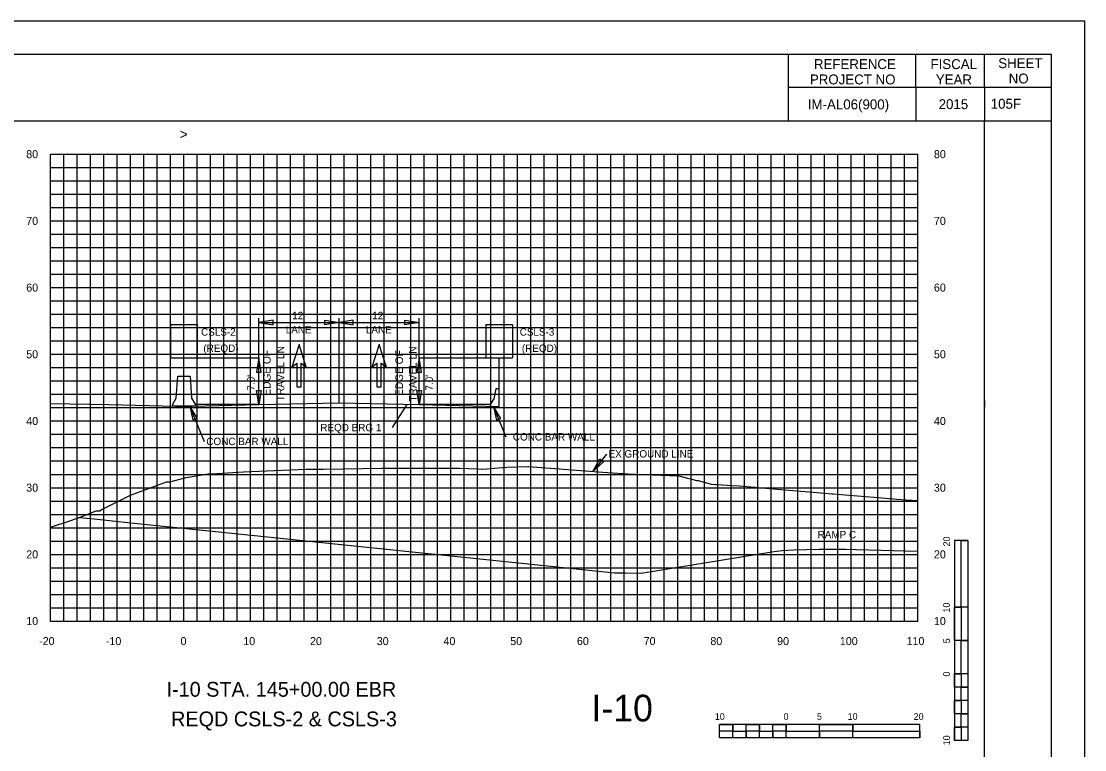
# Model space of a CAD drawing. Extents: x 2193008 to 2198143, y 1236112 to 1237864.
# Drawn here: x 2195038.5 to 2195197.9, y 1237228.8 to 1237338 of the extents above; entities that cross this region are included whole.
import ezdxf

# ---------------------------------------------------------------- set-up
doc = ezdxf.new("R2010")
doc.units = 0
for name, color, linetype in [('10', 7, 'Continuous'), ('2', 7, 'Continuous'), ('3', 7, 'Continuous'), ('31', 7, 'Continuous'), ('60', 7, 'Continuous'), ('ANNO-SHT', 7, 'Continuous'), ('CL-CNST', 7, 'Continuous'), ('GSDIMS', 7, 'Continuous'), ('Level 1', 7, 'Continuous'), ('Level 28', 7, 'Continuous'), ('Level 33', 7, 'Continuous'), ('Level 55', 7, 'Continuous'), ('Level 6', 7, 'Continuous'), ('Level 62', 7, 'Continuous'), ('M-ROADS', 7, 'Continuous'), ('SHT-BDR', 7, 'Continuous'), ('SHT-BNDRY', 7, 'Continuous')]:
    doc.layers.add(name, color=color, linetype=linetype)

msp = doc.modelspace()

# ---------------------------------------------------------------- linework, layer by layer
for points in [[(2195061.19, 1237280.61), (2195061.72, 1237281.52), (2195061.94, 1237284.85), (2195063.78, 1237284.85), (2195064, 1237281.52), (2195064.53, 1237280.61), (2195064.53, 1237280.35), (2195061.19, 1237280.35)], [(2195110.11, 1237280.29), (2195110.1, 1237282.94), (2195109.6, 1237282.94), (2195109.32, 1237281.41), (2195108.74, 1237280.58), (2195108.74, 1237280.32)]]:
    msp.add_lwpolyline(points, close=True)
at = {"layer": '2'}
msp.add_lwpolyline([(2195182.83, 1237281.19), (2195182.84, 1237280.19)], dxfattribs=at)
msp.add_lwpolyline([(2195182.83, 1237281.19), (2195182.84, 1237280.19)], dxfattribs=at)
at = {"layer": '3'}
for p, q in [((2195074.11, 1237280.56), (2195074.11, 1237293.53)), ((2195086.11, 1237280.82), (2195086.11, 1237293.53)), ((2195098.11, 1237280.56), (2195098.11, 1237293.53)), ((2195062.86, 1237284.85), (2195062.86, 1237287.56)), ((2195110.1, 1237282.94), (2195110.1, 1237287.56)), ((2195065.95, 1237274.99), (2195063.74, 1237280.35)), ((2195094.1, 1237277.11), (2195096.3, 1237280.6)), ((2195111.15, 1237275.68), (2195109.24, 1237280.3)), ((2195126.18, 1237273.12), (2195124.16, 1237270.56))]:
    msp.add_line(p, q, dxfattribs=at)
at = {"layer": '60'}
for p, q in [((2195042.86, 1237248.11), (2195042.86, 1237318.11)), ((2195172.86, 1237248.11), (2195172.86, 1237318.11)), ((2195172.92, 1237308.11), (2195172.86, 1237308.11)), ((2195172.92, 1237298.11), (2195172.86, 1237298.11)), ((2195172.92, 1237288.11), (2195172.86, 1237288.11)), ((2195172.92, 1237278.11), (2195172.86, 1237278.11)), ((2195172.92, 1237268.11), (2195172.86, 1237268.11)), ((2195172.92, 1237258.11), (2195172.86, 1237258.11)), ((2195042.86, 1237248.05), (2195042.86, 1237248.11)), ((2195042.86, 1237248.11), (2195172.86, 1237248.11)), ((2195052.86, 1237248.05), (2195052.86, 1237248.11)), ((2195062.86, 1237248.05), (2195062.86, 1237248.11)), ((2195072.86, 1237248.05), (2195072.86, 1237248.11)), ((2195082.86, 1237248.05), (2195082.86, 1237248.11)), ((2195092.86, 1237248.05), (2195092.86, 1237248.11)), ((2195102.86, 1237248.05), (2195102.86, 1237248.11)), ((2195112.86, 1237248.05), (2195112.86, 1237248.11)), ((2195122.86, 1237248.05), (2195122.86, 1237248.11)), ((2195132.86, 1237248.05), (2195132.86, 1237248.11)), ((2195142.86, 1237248.05), (2195142.86, 1237248.11)), ((2195152.86, 1237248.05), (2195152.86, 1237248.11)), ((2195162.86, 1237248.05), (2195162.86, 1237248.11)), ((2195172.86, 1237248.05), (2195172.86, 1237248.11)), ((2195172.92, 1237248.11), (2195172.86, 1237248.11))]:
    msp.add_line(p, q, dxfattribs=at)
at = {"layer": 'CL-CNST'}
for points in [[(2195042.86, 1237280.75), (2195051.61, 1237280.56), (2195061.61, 1237280.34), (2195062.86, 1237280.31)], [(2195062.86, 1237280.31), (2195064.11, 1237280.34), (2195074.11, 1237280.56), (2195086.11, 1237280.82), (2195098.11, 1237280.56), (2195110.11, 1237280.29)], [(2195047.23, 1237263.66), (2195049.42, 1237263.44), (2195054.92, 1237262.86), (2195073.44, 1237260.94), (2195116.86, 1237256.42), (2195127.39, 1237255.32), (2195129.05, 1237255.32), (2195131.41, 1237255.31), (2195150.98, 1237258.47), (2195152.49, 1237258.71), (2195154.2, 1237258.77), (2195158.02, 1237258.91), (2195158.09, 1237258.91), (2195162.03, 1237258.88), (2195163.68, 1237258.84), (2195172.86, 1237258.6)]]:
    msp.add_lwpolyline(points, dxfattribs=at)
at = {"layer": 'GSDIMS'}
for p, q in [((2195060.86, 1237292.56), (2195064.86, 1237292.56)), ((2195060.86, 1237292.56), (2195060.86, 1237287.56)), ((2195064.86, 1237292.56), (2195064.86, 1237287.56)), ((2195074.11, 1237292.87), (2195086.11, 1237292.87)), ((2195086.11, 1237292.87), (2195098.11, 1237292.87)), ((2195108.1, 1237292.56), (2195112.1, 1237292.56)), ((2195108.1, 1237292.56), (2195108.1, 1237287.56)), ((2195112.1, 1237292.56), (2195112.1, 1237287.56)), ((2195060.86, 1237287.56), (2195064.86, 1237287.56)), ((2195064.86, 1237287.56), (2195074.11, 1237287.56)), ((2195098.11, 1237287.56), (2195108.1, 1237287.56)), ((2195108.1, 1237287.56), (2195112.1, 1237287.56)), ((2195074.11, 1237280.56), (2195064.53, 1237280.56)), ((2195108.74, 1237280.56), (2195098.11, 1237280.56))]:
    msp.add_line(p, q, dxfattribs=at)
for points in [[(2195074.11, 1237292.87), (2195076.24, 1237292.52), (2195076.24, 1237293.21)], [(2195086.11, 1237292.87), (2195083.98, 1237292.52), (2195083.98, 1237293.21)], [(2195086.11, 1237292.87), (2195088.24, 1237292.52), (2195088.24, 1237293.21)], [(2195098.11, 1237292.87), (2195095.98, 1237292.52), (2195095.98, 1237293.21)], [(2195074.11, 1237287.56), (2195073.76, 1237285.43), (2195074.46, 1237285.43)], [(2195098.11, 1237287.56), (2195097.76, 1237285.43), (2195098.46, 1237285.43)], [(2195074.11, 1237280.56), (2195073.76, 1237282.69), (2195074.46, 1237282.69)], [(2195098.11, 1237280.56), (2195097.76, 1237282.69), (2195098.46, 1237282.69)], [(2195063.74, 1237280.35), (2195064.22, 1237278.26), (2195064.86, 1237278.54)], [(2195109.24, 1237280.3), (2195109.72, 1237278.22), (2195110.37, 1237278.5)], [(2195124.16, 1237270.56), (2195125.19, 1237272.44), (2195125.73, 1237271.99)]]:
    msp.add_lwpolyline(points, close=True, dxfattribs=at)
at = {"layer": 'Level 1'}
for p, q in [((2195178.33, 1237260.19), (2195178.33, 1237230.19)), ((2195180.33, 1237260.19), (2195178.33, 1237260.19)), ((2195180.33, 1237260.19), (2195180.33, 1237250.19)), ((2195180.33, 1237260.19), (2195180.33, 1237230.19)), ((2195179.33, 1237250.19), (2195178.33, 1237250.19)), ((2195180.33, 1237250.19), (2195178.33, 1237250.19)), ((2195179.33, 1237250.19), (2195179.33, 1237245.19)), ((2195180.33, 1237245.19), (2195178.33, 1237245.19)), ((2195180.33, 1237245.19), (2195179.33, 1237245.19)), ((2195180.33, 1237245.19), (2195180.33, 1237240.19)), ((2195179.33, 1237240.19), (2195178.33, 1237240.19)), ((2195180.33, 1237240.19), (2195178.33, 1237240.19)), ((2195179.33, 1237240.19), (2195179.33, 1237238.19)), ((2195180.33, 1237238.19), (2195179.33, 1237238.19)), ((2195180.33, 1237238.19), (2195180.33, 1237236.19)), ((2195179.33, 1237236.19), (2195178.33, 1237236.19)), ((2195179.33, 1237236.19), (2195179.33, 1237234.19)), ((2195180.33, 1237234.19), (2195179.33, 1237234.19)), ((2195180.33, 1237234.19), (2195180.33, 1237232.19)), ((2195173.13, 1237232.63), (2195143.13, 1237232.63)), ((2195143.13, 1237230.63), (2195143.13, 1237232.63)), ((2195145.13, 1237231.63), (2195145.13, 1237232.63)), ((2195149.13, 1237231.63), (2195149.13, 1237232.63)), ((2195153.13, 1237231.63), (2195153.13, 1237232.63)), ((2195153.13, 1237230.63), (2195153.13, 1237232.63)), ((2195158.13, 1237230.63), (2195158.13, 1237232.63)), ((2195163.13, 1237231.63), (2195163.13, 1237232.63)), ((2195163.13, 1237230.63), (2195163.13, 1237232.63)), ((2195173.13, 1237230.63), (2195173.13, 1237232.63)), ((2195145.13, 1237231.63), (2195143.13, 1237231.63)), ((2195147.13, 1237230.63), (2195147.13, 1237231.63)), ((2195149.13, 1237231.63), (2195147.13, 1237231.63)), ((2195151.13, 1237230.63), (2195151.13, 1237231.63)), ((2195153.13, 1237231.63), (2195151.13, 1237231.63)), ((2195158.13, 1237230.63), (2195158.13, 1237231.63)), ((2195163.13, 1237231.63), (2195158.13, 1237231.63)), ((2195179.33, 1237232.19), (2195178.33, 1237232.19)), ((2195179.33, 1237232.19), (2195179.33, 1237230.19)), ((2195173.13, 1237230.63), (2195143.13, 1237230.63)), ((2195147.13, 1237230.63), (2195145.13, 1237230.63)), ((2195151.13, 1237230.63), (2195149.13, 1237230.63)), ((2195158.13, 1237230.63), (2195153.13, 1237230.63)), ((2195173.13, 1237230.63), (2195163.13, 1237230.63)), ((2195180.33, 1237230.19), (2195178.33, 1237230.19))]:
    msp.add_line(p, q, dxfattribs=at)
for points in [[(2195179.33, 1237250.19), (2195179.33, 1237260.19), (2195180.33, 1237260.19), (2195180.33, 1237250.19)], [(2195178.33, 1237245.19), (2195178.33, 1237250.19), (2195179.33, 1237250.19), (2195179.33, 1237245.19)], [(2195179.33, 1237240.19), (2195179.33, 1237245.19), (2195180.33, 1237245.19), (2195180.33, 1237240.19)], [(2195178.33, 1237238.19), (2195178.33, 1237240.19), (2195179.33, 1237240.19), (2195179.33, 1237238.19)], [(2195179.33, 1237236.19), (2195179.33, 1237238.19), (2195180.33, 1237238.19), (2195180.33, 1237236.19)], [(2195178.33, 1237234.19), (2195178.33, 1237236.19), (2195179.33, 1237236.19), (2195179.33, 1237234.19)], [(2195179.33, 1237232.19), (2195179.33, 1237234.19), (2195180.33, 1237234.19), (2195180.33, 1237232.19)], [(2195143.13, 1237232.63), (2195145.13, 1237232.63), (2195145.13, 1237231.63), (2195143.13, 1237231.63)], [(2195147.13, 1237232.63), (2195149.13, 1237232.63), (2195149.13, 1237231.63), (2195147.13, 1237231.63)], [(2195151.13, 1237232.63), (2195153.13, 1237232.63), (2195153.13, 1237231.63), (2195151.13, 1237231.63)], [(2195158.13, 1237232.63), (2195163.13, 1237232.63), (2195163.13, 1237231.63), (2195158.13, 1237231.63)], [(2195145.13, 1237231.63), (2195147.13, 1237231.63), (2195147.13, 1237230.63), (2195145.13, 1237230.63)], [(2195149.13, 1237231.63), (2195151.13, 1237231.63), (2195151.13, 1237230.63), (2195149.13, 1237230.63)], [(2195153.13, 1237231.63), (2195158.13, 1237231.63), (2195158.13, 1237230.63), (2195153.13, 1237230.63)], [(2195163.13, 1237231.63), (2195173.13, 1237231.63), (2195173.13, 1237230.63), (2195163.13, 1237230.63)], [(2195178.33, 1237230.19), (2195178.33, 1237232.19), (2195179.33, 1237232.19), (2195179.33, 1237230.19)]]:
    msp.add_lwpolyline(points, close=True, dxfattribs=at)
at = {"layer": 'Level 28'}
for p, q in [((2195080.11, 1237289.56), (2195079.02, 1237286.16)), ((2195081.2, 1237286.16), (2195080.11, 1237289.56)), ((2195092.11, 1237289.56), (2195091.02, 1237286.16)), ((2195093.2, 1237286.16), (2195092.11, 1237289.56)), ((2195079.02, 1237286.16), (2195079.78, 1237286.8)), ((2195079.78, 1237286.8), (2195079.78, 1237283.23)), ((2195080.44, 1237283.23), (2195080.44, 1237286.8)), ((2195080.44, 1237286.8), (2195081.2, 1237286.16)), ((2195091.02, 1237286.16), (2195091.78, 1237286.8)), ((2195091.78, 1237286.8), (2195091.78, 1237283.23)), ((2195092.44, 1237283.23), (2195092.44, 1237286.8)), ((2195092.44, 1237286.8), (2195093.2, 1237286.16)), ((2195079.78, 1237283.23), (2195080.44, 1237283.23)), ((2195091.78, 1237283.23), (2195092.44, 1237283.23))]:
    msp.add_line(p, q, dxfattribs=at)
at = {"layer": 'Level 6'}
for p, q in [((2195153.41, 1237333.04), (2195153.41, 1237323.05)), ((2195172.57, 1237328.04), (2195172.57, 1237333.04)), ((2195182.86, 1237328.17), (2195182.86, 1237333.04)), ((2195192.86, 1237328.1), (2195153.41, 1237328.1)), ((2195182.86, 1237328.17), (2195182.86, 1237323.05)), ((2195172.57, 1237328.04), (2195172.57, 1237323.05)), ((2195192.86, 1237323.05), (2195154.62, 1237323.05))]:
    msp.add_line(p, q, dxfattribs=at)
at = {"layer": 'Level 62'}
for p, q in [((2195042.86, 1237318.11), (2195172.86, 1237318.11)), ((2195044.86, 1237248.11), (2195044.86, 1237318.11)), ((2195046.86, 1237248.11), (2195046.86, 1237318.11)), ((2195048.86, 1237248.11), (2195048.86, 1237318.11)), ((2195050.86, 1237248.11), (2195050.86, 1237318.11)), ((2195052.86, 1237248.11), (2195052.86, 1237318.11)), ((2195054.86, 1237248.11), (2195054.86, 1237318.11)), ((2195056.86, 1237248.11), (2195056.86, 1237318.11)), ((2195058.86, 1237248.11), (2195058.86, 1237318.11)), ((2195060.86, 1237248.11), (2195060.86, 1237318.11)), ((2195062.86, 1237248.11), (2195062.86, 1237318.11)), ((2195064.86, 1237248.11), (2195064.86, 1237318.11)), ((2195066.86, 1237248.11), (2195066.86, 1237318.11)), ((2195068.86, 1237248.11), (2195068.86, 1237318.11)), ((2195070.86, 1237248.11), (2195070.86, 1237318.11)), ((2195072.86, 1237248.11), (2195072.86, 1237318.11)), ((2195074.86, 1237248.11), (2195074.86, 1237318.11)), ((2195076.86, 1237248.11), (2195076.86, 1237318.11)), ((2195078.86, 1237248.11), (2195078.86, 1237318.11)), ((2195080.86, 1237248.11), (2195080.86, 1237318.11)), ((2195082.86, 1237248.11), (2195082.86, 1237318.11)), ((2195084.86, 1237248.11), (2195084.86, 1237318.11)), ((2195086.86, 1237248.11), (2195086.86, 1237318.11)), ((2195088.86, 1237248.11), (2195088.86, 1237318.11)), ((2195090.86, 1237248.11), (2195090.86, 1237318.11)), ((2195092.86, 1237248.11), (2195092.86, 1237318.11)), ((2195094.86, 1237248.11), (2195094.86, 1237318.11)), ((2195096.86, 1237248.11), (2195096.86, 1237318.11)), ((2195098.86, 1237248.11), (2195098.86, 1237318.11)), ((2195100.86, 1237248.11), (2195100.86, 1237318.11)), ((2195102.86, 1237248.11), (2195102.86, 1237318.11)), ((2195104.86, 1237248.11), (2195104.86, 1237318.11)), ((2195106.86, 1237248.11), (2195106.86, 1237318.11)), ((2195108.86, 1237248.11), (2195108.86, 1237318.11)), ((2195110.86, 1237248.11), (2195110.86, 1237318.11)), ((2195112.86, 1237248.11), (2195112.86, 1237318.11)), ((2195114.86, 1237248.11), (2195114.86, 1237318.11)), ((2195116.86, 1237248.11), (2195116.86, 1237318.11)), ((2195118.86, 1237248.11), (2195118.86, 1237318.11)), ((2195120.86, 1237248.11), (2195120.86, 1237318.11)), ((2195122.86, 1237248.11), (2195122.86, 1237318.11)), ((2195124.86, 1237248.11), (2195124.86, 1237318.11)), ((2195126.86, 1237248.11), (2195126.86, 1237318.11)), ((2195128.86, 1237248.11), (2195128.86, 1237318.11)), ((2195130.86, 1237248.11), (2195130.86, 1237318.11)), ((2195132.86, 1237248.11), (2195132.86, 1237318.11)), ((2195134.86, 1237248.11), (2195134.86, 1237318.11)), ((2195136.86, 1237248.11), (2195136.86, 1237318.11)), ((2195138.86, 1237248.11), (2195138.86, 1237318.11)), ((2195140.86, 1237248.11), (2195140.86, 1237318.11)), ((2195142.86, 1237248.11), (2195142.86, 1237318.11)), ((2195144.86, 1237248.11), (2195144.86, 1237318.11)), ((2195146.86, 1237248.11), (2195146.86, 1237318.11)), ((2195148.86, 1237248.11), (2195148.86, 1237318.11)), ((2195150.86, 1237248.11), (2195150.86, 1237318.11)), ((2195152.86, 1237248.11), (2195152.86, 1237318.11)), ((2195154.86, 1237248.11), (2195154.86, 1237318.11)), ((2195156.86, 1237248.11), (2195156.86, 1237318.11)), ((2195158.86, 1237248.11), (2195158.86, 1237318.11)), ((2195160.86, 1237248.11), (2195160.86, 1237318.11)), ((2195162.86, 1237248.11), (2195162.86, 1237318.11)), ((2195164.86, 1237248.11), (2195164.86, 1237318.11)), ((2195166.86, 1237248.11), (2195166.86, 1237318.11)), ((2195168.86, 1237248.11), (2195168.86, 1237318.11)), ((2195170.86, 1237248.11), (2195170.86, 1237318.11)), ((2195172.86, 1237248.11), (2195172.86, 1237318.11)), ((2195042.86, 1237316.11), (2195172.86, 1237316.11)), ((2195042.86, 1237314.11), (2195172.86, 1237314.11)), ((2195042.86, 1237312.11), (2195172.86, 1237312.11)), ((2195042.86, 1237310.11), (2195172.86, 1237310.11)), ((2195042.86, 1237308.11), (2195172.86, 1237308.11)), ((2195042.86, 1237306.11), (2195172.86, 1237306.11)), ((2195042.86, 1237304.11), (2195172.86, 1237304.11)), ((2195042.86, 1237302.11), (2195172.86, 1237302.11)), ((2195042.86, 1237300.11), (2195172.86, 1237300.11)), ((2195042.86, 1237298.11), (2195172.86, 1237298.11)), ((2195042.86, 1237296.11), (2195172.86, 1237296.11)), ((2195042.86, 1237294.11), (2195172.86, 1237294.11)), ((2195042.86, 1237292.11), (2195172.86, 1237292.11)), ((2195042.86, 1237290.11), (2195172.86, 1237290.11)), ((2195042.86, 1237288.11), (2195172.86, 1237288.11)), ((2195042.86, 1237286.11), (2195172.86, 1237286.11)), ((2195042.86, 1237284.11), (2195172.86, 1237284.11)), ((2195042.86, 1237282.11), (2195172.86, 1237282.11)), ((2195042.86, 1237280.11), (2195172.86, 1237280.11)), ((2195042.86, 1237278.11), (2195172.86, 1237278.11)), ((2195042.86, 1237276.11), (2195172.86, 1237276.11)), ((2195042.86, 1237274.11), (2195172.86, 1237274.11)), ((2195042.86, 1237272.11), (2195172.86, 1237272.11)), ((2195042.86, 1237270.11), (2195172.86, 1237270.11)), ((2195042.86, 1237268.11), (2195172.86, 1237268.11)), ((2195042.86, 1237266.11), (2195172.86, 1237266.11)), ((2195042.86, 1237264.11), (2195172.86, 1237264.11)), ((2195042.86, 1237262.11), (2195172.86, 1237262.11)), ((2195042.86, 1237260.11), (2195172.86, 1237260.11)), ((2195042.86, 1237258.11), (2195172.86, 1237258.11)), ((2195042.86, 1237256.11), (2195172.86, 1237256.11)), ((2195042.86, 1237254.11), (2195172.86, 1237254.11)), ((2195042.86, 1237252.11), (2195172.86, 1237252.11)), ((2195042.86, 1237250.11), (2195172.86, 1237250.11)), ((2195042.86, 1237248.11), (2195172.86, 1237248.11))]:
    msp.add_line(p, q, dxfattribs=at)
msp.add_lwpolyline([(2194857.86, 1237118.04), (2195197.86, 1237118.04), (2195197.86, 1237338.04), (2194857.86, 1237338.04)], close=True, dxfattribs=at)
at = {"layer": 'M-ROADS'}
msp.add_lwpolyline([(2195042.86, 1237262.2), (2195045.92, 1237263.21), (2195047.32, 1237263.69), (2195049.73, 1237264.63), (2195049.78, 1237264.66), (2195050.17, 1237264.64), (2195050.24, 1237264.63), (2195050.48, 1237264.78), (2195054.88, 1237267), (2195060.26, 1237269), (2195060.53, 1237269), (2195060.75, 1237269), (2195063.21, 1237269.65), (2195066.5, 1237270.21), (2195066.71, 1237270.21), (2195067.01, 1237270.21), (2195070.18, 1237270.39), (2195071.8, 1237270.51), (2195077.6, 1237270.74), (2195081.18, 1237270.88), (2195083.74, 1237270.91), (2195092.51, 1237271.04), (2195095.01, 1237271.04), (2195104.15, 1237271.05), (2195106.94, 1237270.93), (2195107.65, 1237270.9), (2195109.41, 1237271.05), (2195110.54, 1237271.15), (2195110.78, 1237271.14), (2195111.24, 1237271.18), (2195114.39, 1237271.3), (2195114.5, 1237271.3), (2195125.66, 1237270.45), (2195130.17, 1237270.16), (2195130.52, 1237270.16), (2195136.95, 1237269.88), (2195137.02, 1237269.88), (2195138.33, 1237269.55), (2195138.77, 1237269.43), (2195139.66, 1237269.21), (2195139.91, 1237269.2), (2195141.9, 1237268.63), (2195142.54, 1237268.6), (2195142.83, 1237268.58), (2195145, 1237268.46), (2195146.09, 1237268.4), (2195148.4, 1237268.21), (2195150.61, 1237268.01), (2195154.12, 1237267.71), (2195157.77, 1237267.38), (2195159.98, 1237267.19), (2195160.08, 1237267.18), (2195160.15, 1237267.18), (2195162.57, 1237266.98), (2195166.32, 1237266.68), (2195169.72, 1237266.4), (2195171.05, 1237266.31), (2195172.86, 1237266.18)], dxfattribs=at)
at = {"layer": 'SHT-BDR'}
msp.add_lwpolyline([(2194882.86, 1237133.05), (2195182.86, 1237133.05), (2195182.86, 1237323.05), (2194882.86, 1237323.05)], close=True, dxfattribs=at)
at = {"layer": 'SHT-BNDRY'}
msp.add_lwpolyline([(2194870.36, 1237123.04), (2195192.86, 1237123.04), (2195192.86, 1237333.04), (2194870.36, 1237333.04)], close=True, dxfattribs=at)

# ---------------------------------------------------------------- texts
at = {"layer": '10'}
for s, p in [('-20', (2195041.16, 1237244.51)), ('-10', (2195051.16, 1237244.51)), ('0', (2195062.36, 1237244.51)), ('10', (2195071.76, 1237244.51)), ('20', (2195081.76, 1237244.51)), ('30', (2195091.76, 1237244.51)), ('40', (2195101.76, 1237244.51)), ('50', (2195111.76, 1237244.51)), ('60', (2195121.76, 1237244.51)), ('70', (2195131.76, 1237244.51)), ('80', (2195141.76, 1237244.51)), ('90', (2195151.76, 1237244.51)), ('100', (2195161.16, 1237244.51)), ('110', (2195171.16, 1237244.51))]:
    msp.add_text(s, height=1.2, dxfattribs=at).set_placement(p)
at = {"layer": '3'}
msp.add_text('REQD BRG 1', height=1.11, dxfattribs=at).set_placement((2195083.3, 1237276.57))
at = {"layer": '31'}
for s, p in [('80', (2195039.23, 1237317.51)), ('80', (2195175.26, 1237317.51)), ('70', (2195039.23, 1237307.51)), ('70', (2195175.26, 1237307.51)), ('60', (2195039.23, 1237297.51)), ('60', (2195175.26, 1237297.51)), ('50', (2195039.23, 1237287.51)), ('50', (2195175.26, 1237287.51)), ('40', (2195039.23, 1237277.51)), ('40', (2195175.26, 1237277.51)), ('30', (2195039.23, 1237267.51)), ('30', (2195175.26, 1237267.51)), ('20', (2195039.23, 1237257.51)), ('20', (2195175.26, 1237257.51)), ('10', (2195039.23, 1237247.51)), ('10', (2195175.26, 1237247.51))]:
    msp.add_text(s, height=1.2, dxfattribs=at).set_placement(p)
at = {"layer": '60'}
msp.add_text('>', height=1.5, dxfattribs=at).set_placement((2195062.25, 1237320.36))
at = {"layer": 'ANNO-SHT'}
for s, height, p in [(' IM-AL06(900) ', 1.4899, (2195155.81, 1237324.83)), ('2015', 1.49, (2195175.97, 1237324.86)), ('  105F ', 1.49, (2195182.67, 1237324.92))]:
    msp.add_text(s, height=height, rotation=360, dxfattribs=at).set_placement(p)
at = {"layer": 'Level 1'}
for s, height, rotation, p in [('20', 0.999, 90.0572, (2195177.66, 1237259.3)), ('10', 0.999, 90.0572, (2195177.66, 1237249.39)), ('5', 1, 90.0572, (2195177.66, 1237244.78)), ('0', 1, 90.0572, (2195177.66, 1237239.79)), ('10', 0.999, 0.0572, (2195142.43, 1237233.3)), ('0', 1, 0.0572, (2195152.73, 1237233.3)), ('5', 0.999, 0.0572, (2195157.73, 1237233.3)), ('10', 0.999, 0.0572, (2195162.33, 1237233.3)), ('20', 0.999, 0.0572, (2195172.23, 1237233.3)), ('10', 0.999, 90.0572, (2195177.66, 1237229.49))]:
    msp.add_text(s, height=height, rotation=rotation, dxfattribs=at).set_placement(p)
at = {"layer": 'Level 33'}
msp.add_text('I-10', height=3.998, rotation=360, dxfattribs=at).set_placement((2195123.93, 1237233.07))
at = {"layer": 'Level 55'}
for s, height, p in [("12'", 1.11, (2195079.09, 1237293.37)), ("12'", 1.11, (2195091.09, 1237293.37)), ('LANE', 1.11, (2195078.12, 1237291.25)), ('LANE', 1.11, (2195090.13, 1237291.25)), ('CONC BAR WALL', 1.1105, (2195066.22, 1237274.49)), ('CONC BAR WALL', 1.1105, (2195112.16, 1237275.18)), ('EX GROUND LINE', 1.1105, (2195126.5, 1237272.63)), ('RAMP C', 1.11, (2195157.83, 1237260.52)), ('I-10 STA. 145+00.00 EBR', 2.2209, (2195060.26, 1237236.77)), ('REQD CSLS-2 & CSLS-3', 2.2209, (2195060.94, 1237232.33))]:
    msp.add_text(s, height=height, dxfattribs=at).set_placement(p)
for s, height, rotation, p in [('CSLS-2', 1.11, 360, (2195065.43, 1237290.9)), ('CSLS-3', 1.11, 360, (2195113.18, 1237290.9)), ('(REQD)', 1.11, 360, (2195065.78, 1237288.46)), ('EDGE OF', 1.135, 90, (2195075.86, 1237281.92)), ('TRAVEL LN', 1.135, 90, (2195077.9, 1237281.07)), ('EDGE OF', 1.135, 90, (2195095.69, 1237281.88)), ('TRAVEL LN', 1.135, 90, (2195097.73, 1237281.02)), ('(REQD)', 1.11, 360, (2195113.51, 1237288.46)), ("7.0'", 1.11, 90, (2195073.46, 1237282.67)), ("7.0'", 1.11, 90, (2195100.17, 1237282.67))]:
    msp.add_text(s, height=height, rotation=rotation, dxfattribs=at).set_placement(p)
at = {"layer": 'Level 6'}
for s, p in [('REFERENCE', (2195157.28, 1237330.87)), ('FISCAL', (2195174.75, 1237330.87)), ('SHEET', (2195184.9, 1237331.01)), ('PROJECT NO', (2195156.68, 1237328.57)), ('YEAR', (2195175.55, 1237328.57)), ('NO', (2195186.47, 1237328.71))]:
    msp.add_text(s, height=1.488, dxfattribs=at).set_placement(p)

doc.saveas('drawing.dxf')
